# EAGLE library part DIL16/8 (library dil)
SOCKET Dual In Line, 8 pins used
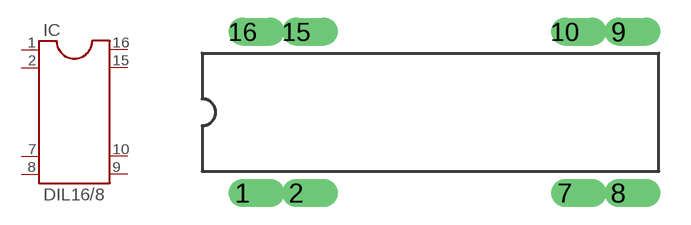
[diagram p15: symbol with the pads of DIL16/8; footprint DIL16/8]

Designator prefix IC

## DIL16/8  [DIL16/8]
1  1  pas
2  2  pas
7  7  pas
8  8  pas
9  9  pas
10  10  pas
15  15  pas
16  16  pas

## Footprint DIL16/8 (pad centres in mm)
SOCKET Dual In Line, 8 pins used
drill 0.813 offset: 1 -8.89,-3.81; 2 -6.35,-3.81; 7 6.35,-3.81; 8 8.89,-3.81; 9 8.89,3.81; 10 6.35,3.81; 15 -6.35,3.81; 16 -8.89,3.81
